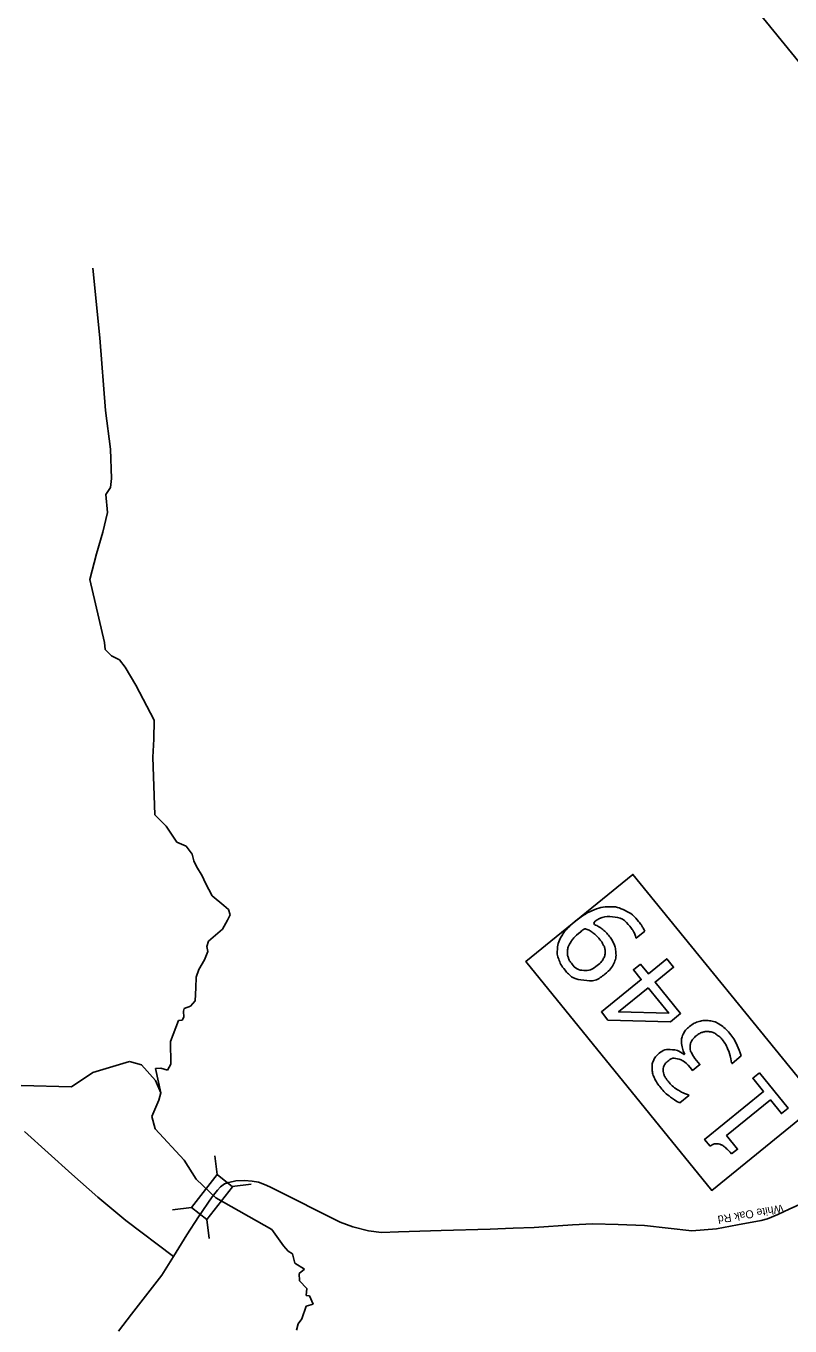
# Model space of a CAD drawing. Extents: x 2596159 to 2598075, y 851667 to 853493.
# Drawn here: x 2597143.5 to 2597207.4, y 851961.3 to 852070 of the extents above; entities that cross this region are included whole.
import ezdxf

# ---------------------------------------------------------------- set-up
doc = ezdxf.new("R2010")
doc.units = 0
doc.layers.add('Old_Level_1', color=7, linetype='Continuous')

msp = doc.modelspace()

# ---------------------------------------------------------------- linework, layer by layer
at = {"layer": 'Old_Level_1'}
for p, q in [((2597375.45, 851861.15), (2597166.09, 852118.74)), ((2597149.04, 852049.77), (2597149.63, 852043.94)), ((2597149.63, 852043.94), (2597150.11, 852037.87)), ((2597150.11, 852037.87), (2597150.51, 852034.63)), ((2597150.51, 852034.63), (2597150.62, 852032.18)), ((2597150.62, 852032.18), (2597150.53, 852031.41)), ((2597150.53, 852031.41), (2597150.12, 852030.83)), ((2597150.12, 852030.83), (2597150.28, 852029.33)), ((2597150.28, 852029.33), (2597149.89, 852027.68)), ((2597149.89, 852027.68), (2597149.35, 852025.87)), ((2597149.35, 852025.87), (2597148.79, 852023.73)), ((2597148.79, 852023.73), (2597150.03, 852018.44)), ((2597150.03, 852018.44), (2597150.08, 852017.87)), ((2597150.08, 852017.87), (2597150.6, 852017.33)), ((2597150.6, 852017.33), (2597151.27, 852017.01)), ((2597151.27, 852017.01), (2597151.75, 852016.38)), ((2597151.75, 852016.38), (2597152.63, 852014.89)), ((2597152.63, 852014.89), (2597154.19, 852011.96)), ((2597154.19, 852011.96), (2597154.16, 852010.36)), ((2597154.16, 852010.36), (2597154.07, 852008.85)), ((2597154.07, 852008.85), (2597154.24, 852004.04)), ((2597154.24, 852004.04), (2597155.18, 852003.09)), ((2597155.18, 852003.09), (2597155.62, 852002.42)), ((2597155.62, 852002.42), (2597156.08, 852001.75)), ((2597156.08, 852001.75), (2597156.86, 852001.4)), ((2597156.86, 852001.4), (2597157.36, 852000.75)), ((2597157.36, 852000.75), (2597157.5, 852000.17)), ((2597157.5, 852000.17), (2597157.71, 851999.71)), ((2597157.71, 851999.71), (2597158.18, 851998.92)), ((2597209.8, 851979.89), (2597194.23, 851999.04)), ((2597158.18, 851998.92), (2597158.48, 851998.32)), ((2597158.48, 851998.32), (2597159.04, 851997.25)), ((2597159.04, 851997.25), (2597160.01, 851996.44)), ((2597160.01, 851996.44), (2597160.4, 851996.12)), ((2597160.4, 851996.12), (2597160.54, 851995.65)), ((2597160.31, 851995.22), (2597159.88, 851994.46)), ((2597160.54, 851995.65), (2597160.31, 851995.22)), ((2597159.88, 851994.46), (2597158.71, 851993.45)), ((2597158.66, 851992.6), (2597158.4, 851991.9)), ((2597158.71, 851993.45), (2597158.59, 851993.02)), ((2597158.59, 851993.02), (2597158.66, 851992.6)), ((2597158.4, 851991.9), (2597157.92, 851991.09)), ((2597157.7, 851990.45), (2597157.67, 851989.54)), ((2597157.92, 851991.09), (2597157.7, 851990.45)), ((2597157.67, 851989.54), (2597157.62, 851988.47)), ((2597157.62, 851988.47), (2597157.21, 851988.03)), ((2597156.67, 851987.09), (2597156.52, 851986.84)), ((2597156.7, 851987.81), (2597156.63, 851987.59)), ((2597156.63, 851987.59), (2597156.67, 851987.09)), ((2597157.21, 851988.03), (2597156.7, 851987.81)), ((2597156.21, 851986.81), (2597155.55, 851985.07)), ((2597156.52, 851986.84), (2597156.21, 851986.81)), ((2597155.55, 851985.07), (2597155.56, 851983.16)), ((2597152.12, 851983.39), (2597149.05, 851982.47)), ((2597153.11, 851983.11), (2597152.12, 851983.39)), ((2597154.29, 851981.8), (2597153.11, 851983.11)), ((2597154.73, 851982.82), (2597154.3, 851982.81)), ((2597154.3, 851982.81), (2597154.73, 851980.78)), ((2597155.29, 851982.67), (2597154.73, 851982.82)), ((2597155.56, 851983.16), (2597155.29, 851982.67)), ((2597149.05, 851982.47), (2597147.27, 851981.28)), ((2597154.73, 851980.78), (2597154.29, 851981.8)), ((2597147.27, 851981.28), (2597143.04, 851981.38)), ((2597154.73, 851980.78), (2597154.58, 851980.16)), ((2597154.58, 851980.16), (2597153.98, 851978.79)), ((2597153.98, 851978.79), (2597154.27, 851977.74)), ((2597147.29, 851973.96), (2597143.34, 851977.54)), ((2597154.27, 851977.74), (2597156.68, 851975.13)), ((2597156.68, 851975.13), (2597157.7, 851973.53)), ((2597159.46, 851973.92), (2597159.26, 851975.5)), ((2597149.46, 851972.03), (2597147.29, 851973.96)), ((2597157.7, 851973.53), (2597159.34, 851971.98)), ((2597160.06, 851973.15), (2597159.72, 851972.91)), ((2597160.43, 851973.26), (2597160.06, 851973.15)), ((2597161.01, 851973.39), (2597160.43, 851973.26)), ((2597160.71, 851972.93), (2597162.3, 851973.12)), ((2597161.72, 851973.44), (2597161.01, 851973.39)), ((2597162.37, 851973.37), (2597161.72, 851973.44)), ((2597162.91, 851973.28), (2597162.37, 851973.37)), ((2597163.41, 851973.1), (2597162.91, 851973.28)), ((2597163.85, 851972.89), (2597163.41, 851973.1)), ((2597151.8, 851970.08), (2597149.46, 851972.03)), ((2597159.04, 851972.05), (2597157.89, 851970.39)), ((2597159.47, 851972.63), (2597159.04, 851972.05)), ((2597159.34, 851971.98), (2597164.03, 851969.34)), ((2597159.72, 851972.91), (2597159.47, 851972.63)), ((2597165.54, 851972.05), (2597163.85, 851972.89)), ((2597168.34, 851970.64), (2597165.54, 851972.05)), ((2597209.83, 851972.18), (2597207.3, 851971.02)), ((2597155.71, 851970.98), (2597157.3, 851971.17)), ((2597207.3, 851971.02), (2597206.36, 851970.58)), ((2597155.8, 851967.08), (2597151.8, 851970.08)), ((2597157.89, 851970.39), (2597156.92, 851968.89)), ((2597158.77, 851968.58), (2597158.58, 851970.16)), ((2597169.75, 851969.95), (2597168.34, 851970.64)), ((2597170.81, 851969.55), (2597169.75, 851969.95)), ((2597189.17, 851969.71), (2597185.96, 851969.51)), ((2597190.84, 851969.8), (2597189.17, 851969.71)), ((2597193, 851969.76), (2597190.84, 851969.8)), ((2597195.21, 851969.67), (2597193, 851969.76)), ((2597199.15, 851969.23), (2597195.21, 851969.67)), ((2597202.98, 851969.73), (2597201.21, 851969.39)), ((2597204.95, 851970.07), (2597202.98, 851969.73)), ((2597205.5, 851970.23), (2597204.95, 851970.07)), ((2597206.36, 851970.58), (2597205.5, 851970.23)), ((2597156.92, 851968.89), (2597155.8, 851967.08)), ((2597164.03, 851969.34), (2597164.99, 851967.96)), ((2597172.12, 851969.22), (2597170.81, 851969.55)), ((2597173.2, 851969.09), (2597172.12, 851969.22)), ((2597174.61, 851969.13), (2597173.2, 851969.09)), ((2597178.18, 851969.24), (2597174.61, 851969.13)), ((2597182.29, 851969.37), (2597178.18, 851969.24)), ((2597184.22, 851969.43), (2597182.29, 851969.37)), ((2597185.96, 851969.51), (2597184.22, 851969.43)), ((2597201.21, 851969.39), (2597199.15, 851969.23)), ((2597164.99, 851967.96), (2597165.4, 851967.52)), ((2597165.4, 851967.52), (2597165.74, 851967.3)), ((2597155.8, 851967.08), (2597154.83, 851965.5)), ((2597165.74, 851967.3), (2597165.94, 851966.52)), ((2597165.94, 851966.52), (2597166.74, 851966.01)), ((2597154.83, 851965.5), (2597152.29, 851962.25)), ((2597166.74, 851966.01), (2597166.31, 851965.66)), ((2597166.31, 851965.66), (2597166.33, 851965.02)), ((2597166.33, 851965.02), (2597166.94, 851964.4)), ((2597166.94, 851964.4), (2597166.88, 851963.8)), ((2597166.88, 851963.8), (2597167.18, 851963.77)), ((2597167.18, 851963.77), (2597167.47, 851963.07)), ((2597152.29, 851962.25), (2597151.18, 851960.82)), ((2597166.88, 851962.92), (2597166.52, 851961.86)), ((2597167.47, 851963.07), (2597166.88, 851962.92)), ((2597166.21, 851961.43), (2597166.09, 851960.9)), ((2597166.52, 851961.86), (2597166.21, 851961.43))]:
    msp.add_line(p, q, dxfattribs=at)
for points in [[(2597209.8, 851979.89), (2597194.23, 851999.04), (2597185.26, 851991.75), (2597200.83, 851972.6), (2597209.8, 851979.89)], [(2597195.22, 851994.3), (2597194.51, 851993.72), (2597194.48, 851993.76)], [(2597194.86, 851991.54), (2597195.52, 851990.73), (2597197.06, 851991.98), (2597197.63, 851991.28), (2597196.09, 851990.03), (2597198.22, 851987.41), (2597197.38, 851986.72), (2597192.14, 851986.86), (2597191.59, 851987.54), (2597194.93, 851990.25), (2597194.27, 851991.06), (2597194.86, 851991.54)], [(2597195.5, 851989.55), (2597193.03, 851987.54), (2597197.23, 851987.43), (2597195.5, 851989.55)], [(2597198.52, 851983.97), (2597198.57, 851984.01)], [(2597203.29, 851983.85), (2597202.53, 851983.22), (2597202.48, 851983.28)], [(2597199.56, 851983.46), (2597199.83, 851983.13), (2597199.22, 851982.64), (2597199.01, 851982.89)], [(2597200.69, 851976.3), (2597200.23, 851976.87), (2597205.16, 851980.88), (2597204.25, 851981.99), (2597204.81, 851982.45)], [(2597204.81, 851982.45), (2597207.22, 851979.49), (2597206.66, 851979.03), (2597205.73, 851980.17), (2597202.07, 851977.19), (2597202.99, 851976.05), (2597202.49, 851975.65)], [(2597198.89, 851980.59), (2597198.92, 851980.55), (2597198.15, 851979.93)]]:
    msp.add_lwpolyline(points, dxfattribs=at)
msp.add_lwpolyline([(2597157.3, 851971.17), (2597159.45, 851973.92), (2597160.74, 851972.91), (2597158.58, 851970.16)], close=True, dxfattribs=at)
for points in [[(2597189.41, 851995.13), (2597190.13, 851995.71), (2597190.85, 851996.02), (2597191.56, 851996.33), (2597192.25, 851996.34), (2597192.94, 851996.34), (2597193.57, 851996.02), (2597194.21, 851995.71), (2597194.76, 851995.03), (2597194.92, 851994.84), (2597195.03, 851994.65), (2597195.15, 851994.46), (2597195.22, 851994.3)], [(2597194.48, 851993.76), (2597194.45, 851993.91), (2597194.34, 851994.15), (2597194.23, 851994.38), (2597194.04, 851994.62), (2597193.38, 851995.43), (2597192.52, 851995.5), (2597191.66, 851995.56), (2597190.74, 851994.94), (2597191.23, 851994.77), (2597191.56, 851994.54), (2597191.89, 851994.31), (2597192.18, 851993.95), (2597192.46, 851993.61), (2597192.61, 851993.29), (2597192.77, 851992.96), (2597192.8, 851992.53), (2597192.84, 851992.02), (2597192.63, 851991.58), (2597192.41, 851991.14), (2597191.93, 851990.74), (2597191.09, 851990.06), (2597190.12, 851990.19), (2597189.14, 851990.31), (2597188.5, 851991.1), (2597188.18, 851991.5), (2597188.03, 851991.94), (2597187.87, 851992.38), (2597187.92, 851992.83), (2597187.97, 851993.39), (2597188.31, 851993.95), (2597188.65, 851994.51), (2597189.41, 851995.13)], [(2597189.86, 851994.25), (2597189.29, 851993.79), (2597189.04, 851993.39), (2597188.79, 851992.99), (2597188.76, 851992.63), (2597188.74, 851992.32), (2597188.83, 851992.07), (2597188.92, 851991.81), (2597189.11, 851991.58), (2597189.53, 851991.05), (2597190.11, 851991.01), (2597190.69, 851990.98), (2597191.29, 851991.46), (2597191.64, 851991.75), (2597191.78, 851992.03), (2597191.92, 851992.3), (2597191.9, 851992.67), (2597191.88, 851992.93), (2597191.75, 851993.16), (2597191.63, 851993.39), (2597191.43, 851993.63), (2597191.2, 851993.92), (2597190.89, 851994.15), (2597190.57, 851994.38), (2597190.22, 851994.52), (2597190.14, 851994.46), (2597190.06, 851994.4), (2597189.98, 851994.35), (2597189.86, 851994.25)], [(2597198.29, 851985.09), (2597198.3, 851985.39), (2597198.45, 851985.7), (2597198.6, 851986.01), (2597198.97, 851986.32), (2597199.35, 851986.62), (2597199.77, 851986.74), (2597200.19, 851986.86), (2597200.63, 851986.8), (2597201.11, 851986.73), (2597201.53, 851986.46), (2597201.96, 851986.19), (2597202.32, 851985.75), (2597202.69, 851985.29), (2597202.94, 851984.76), (2597203.19, 851984.23), (2597203.29, 851983.85)], [(2597198.57, 851984.01), (2597198.46, 851984.21), (2597198.37, 851984.51), (2597198.28, 851984.82), (2597198.29, 851985.09)], [(2597202.48, 851983.28), (2597202.43, 851983.76), (2597202.23, 851984.29), (2597202.02, 851984.82), (2597201.7, 851985.22), (2597201.51, 851985.45), (2597201.22, 851985.65), (2597200.93, 851985.85), (2597200.65, 851985.88), (2597200.35, 851985.92), (2597200.09, 851985.85), (2597199.82, 851985.77), (2597199.52, 851985.53), (2597199.23, 851985.29), (2597199.11, 851985.04), (2597199, 851984.79), (2597199.02, 851984.53), (2597199.04, 851984.27), (2597199.19, 851984), (2597199.34, 851983.73), (2597199.56, 851983.46)], [(2597198.15, 851979.93), (2597197.81, 851980.09), (2597197.35, 851980.43), (2597196.89, 851980.78), (2597196.56, 851981.19), (2597196.23, 851981.59), (2597196.06, 851981.95), (2597195.88, 851982.32), (2597195.84, 851982.7), (2597195.81, 851983.11), (2597195.94, 851983.44), (2597196.08, 851983.78), (2597196.42, 851984.06), (2597196.87, 851984.43), (2597197.48, 851984.38), (2597198.08, 851984.33), (2597198.52, 851983.97)], [(2597199.01, 851982.89), (2597198.56, 851983.45), (2597198.05, 851983.59), (2597197.55, 851983.74), (2597197.1, 851983.37), (2597196.9, 851983.21), (2597196.82, 851983.01), (2597196.74, 851982.8), (2597196.77, 851982.57), (2597196.8, 851982.33), (2597196.91, 851982.12), (2597197.02, 851981.91), (2597197.21, 851981.69), (2597197.49, 851981.34), (2597197.93, 851981.05), (2597198.38, 851980.75), (2597198.89, 851980.59)], [(2597202.49, 851975.65), (2597202.3, 851975.88), (2597202.05, 851976.11), (2597201.8, 851976.34), (2597201.61, 851976.42), (2597201.38, 851976.52), (2597201.16, 851976.5), (2597200.94, 851976.48), (2597200.69, 851976.3)]]:
    msp.add_open_spline(points, degree=3, dxfattribs=at)

# ---------------------------------------------------------------- texts
msp.add_text('White Oak Rd', height=0.6695, rotation=189.93, dxfattribs=at).set_placement((2597206.77, 851971.43))

doc.saveas('drawing.dxf')
